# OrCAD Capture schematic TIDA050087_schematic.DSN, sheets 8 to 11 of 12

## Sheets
8 P06: i.MX93 IO/PHY: size C
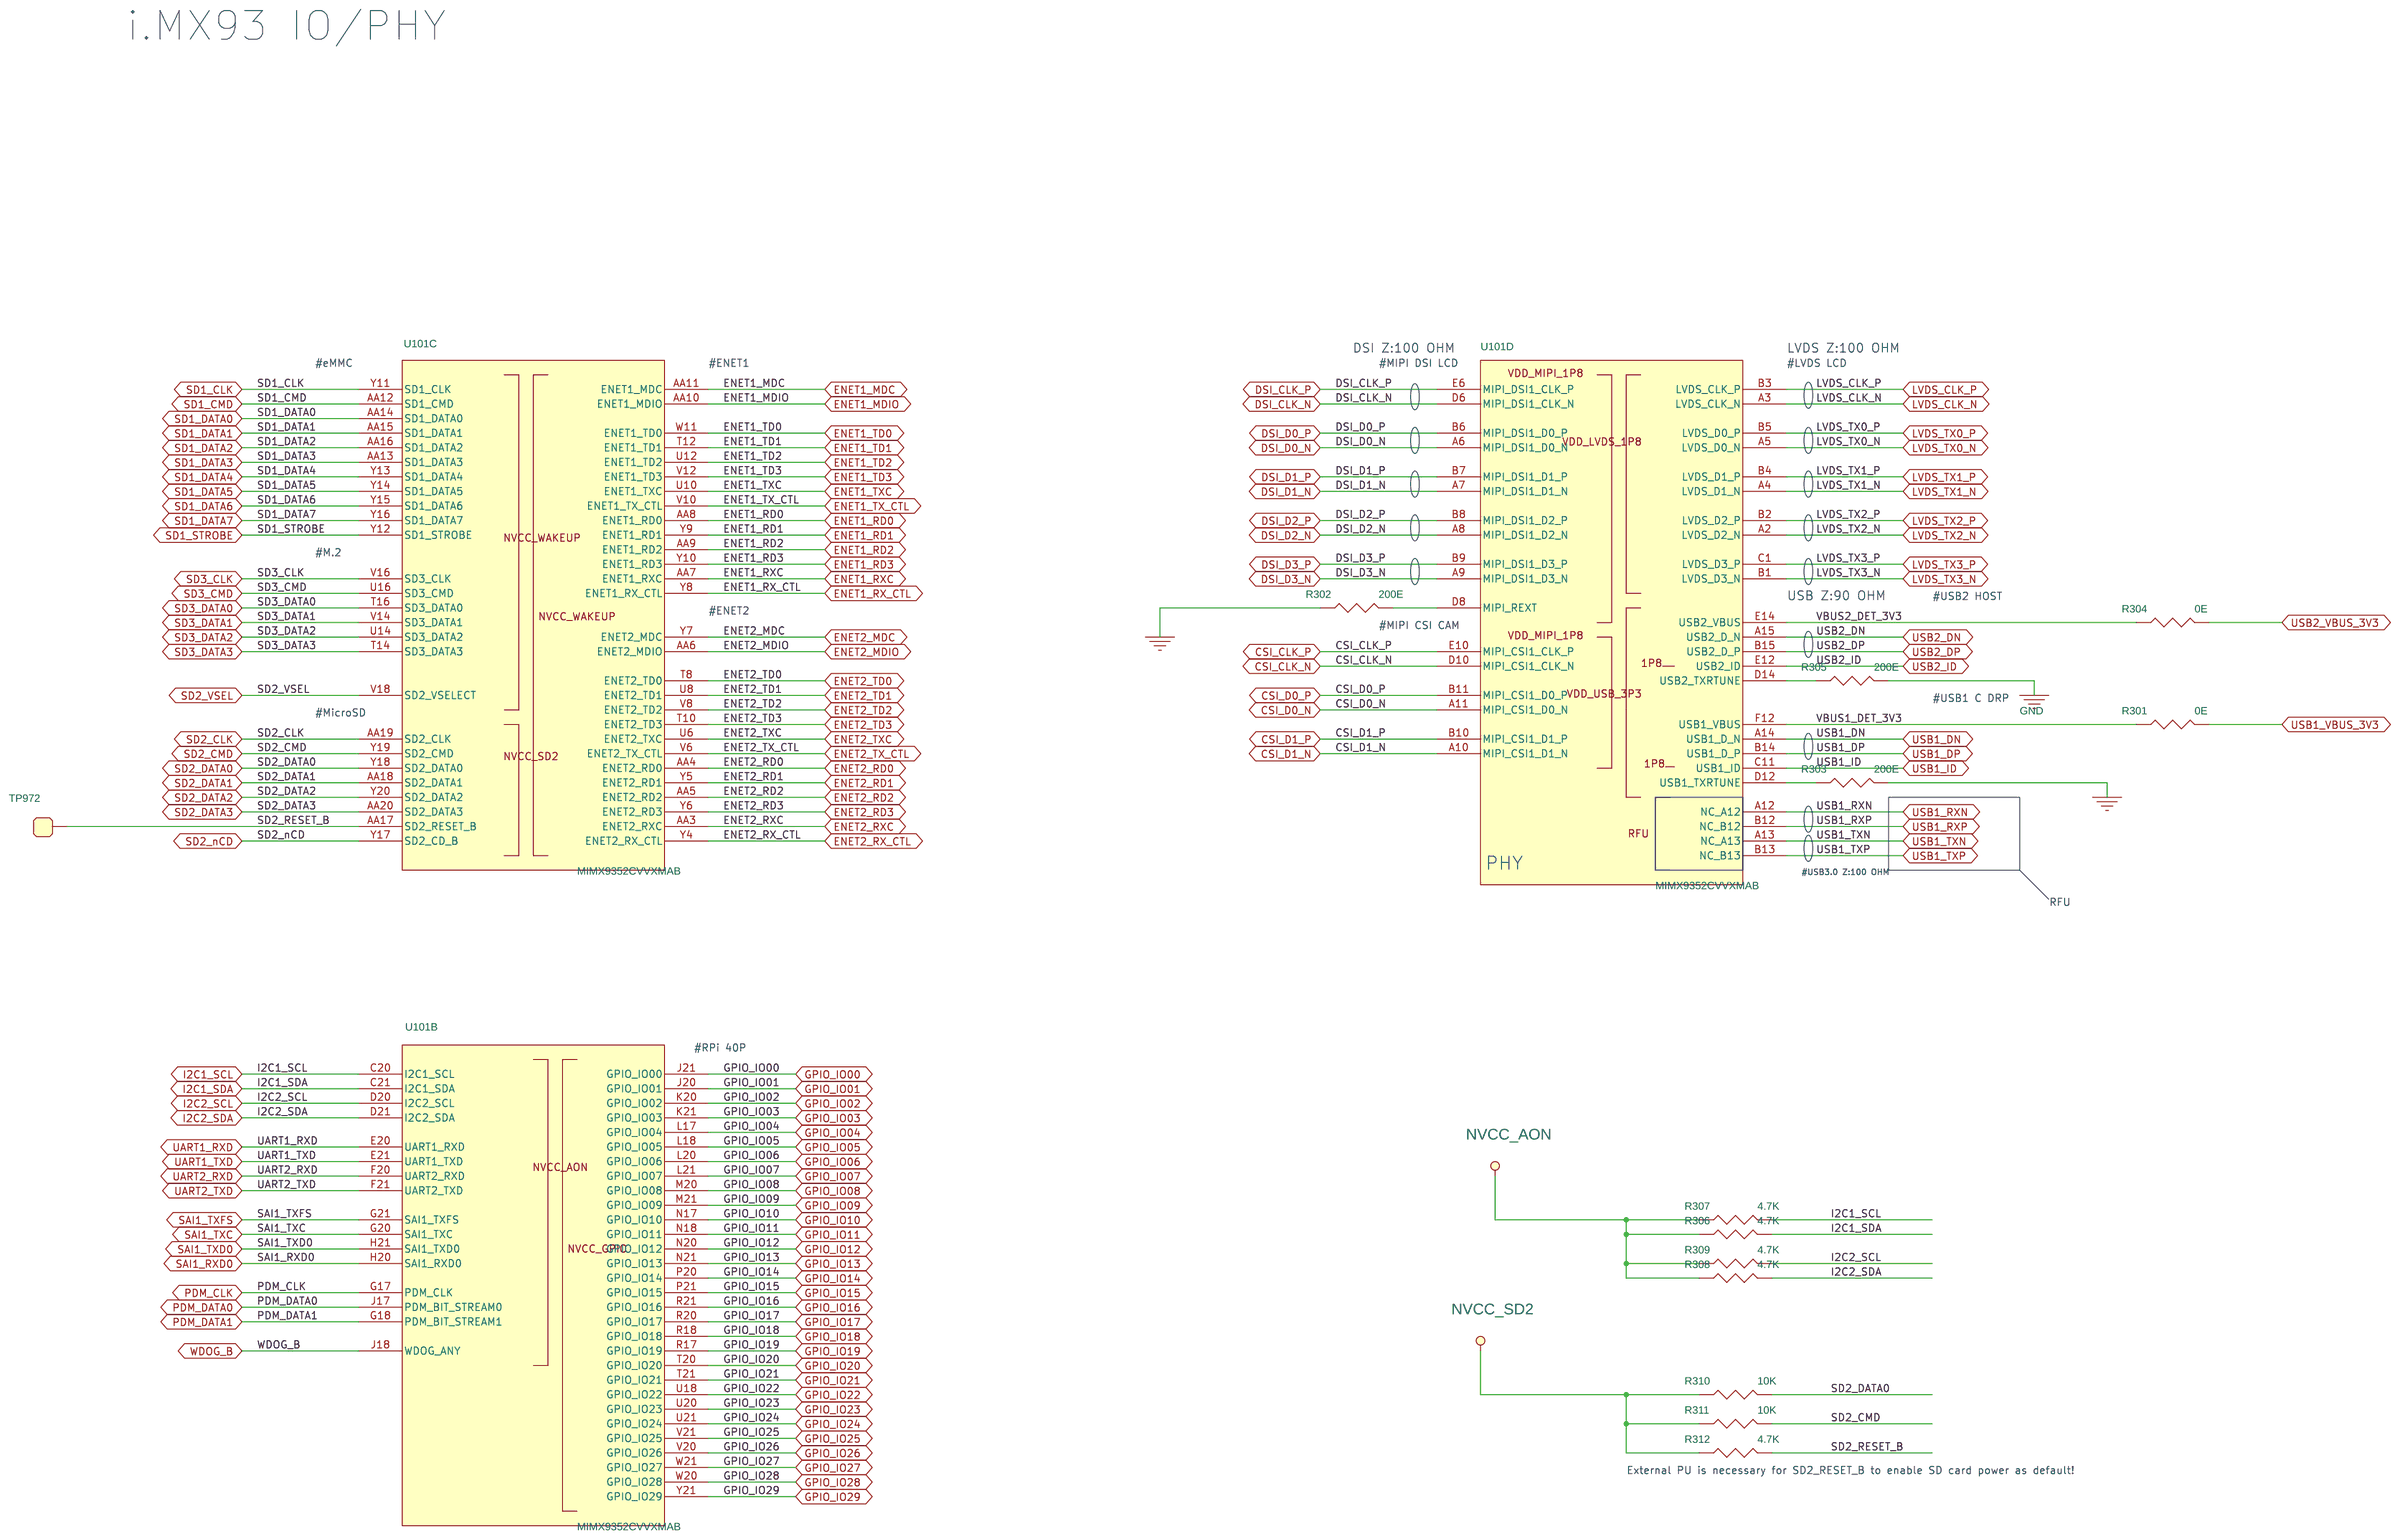
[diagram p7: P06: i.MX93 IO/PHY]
9 P03: POWER ARCHITECTURE
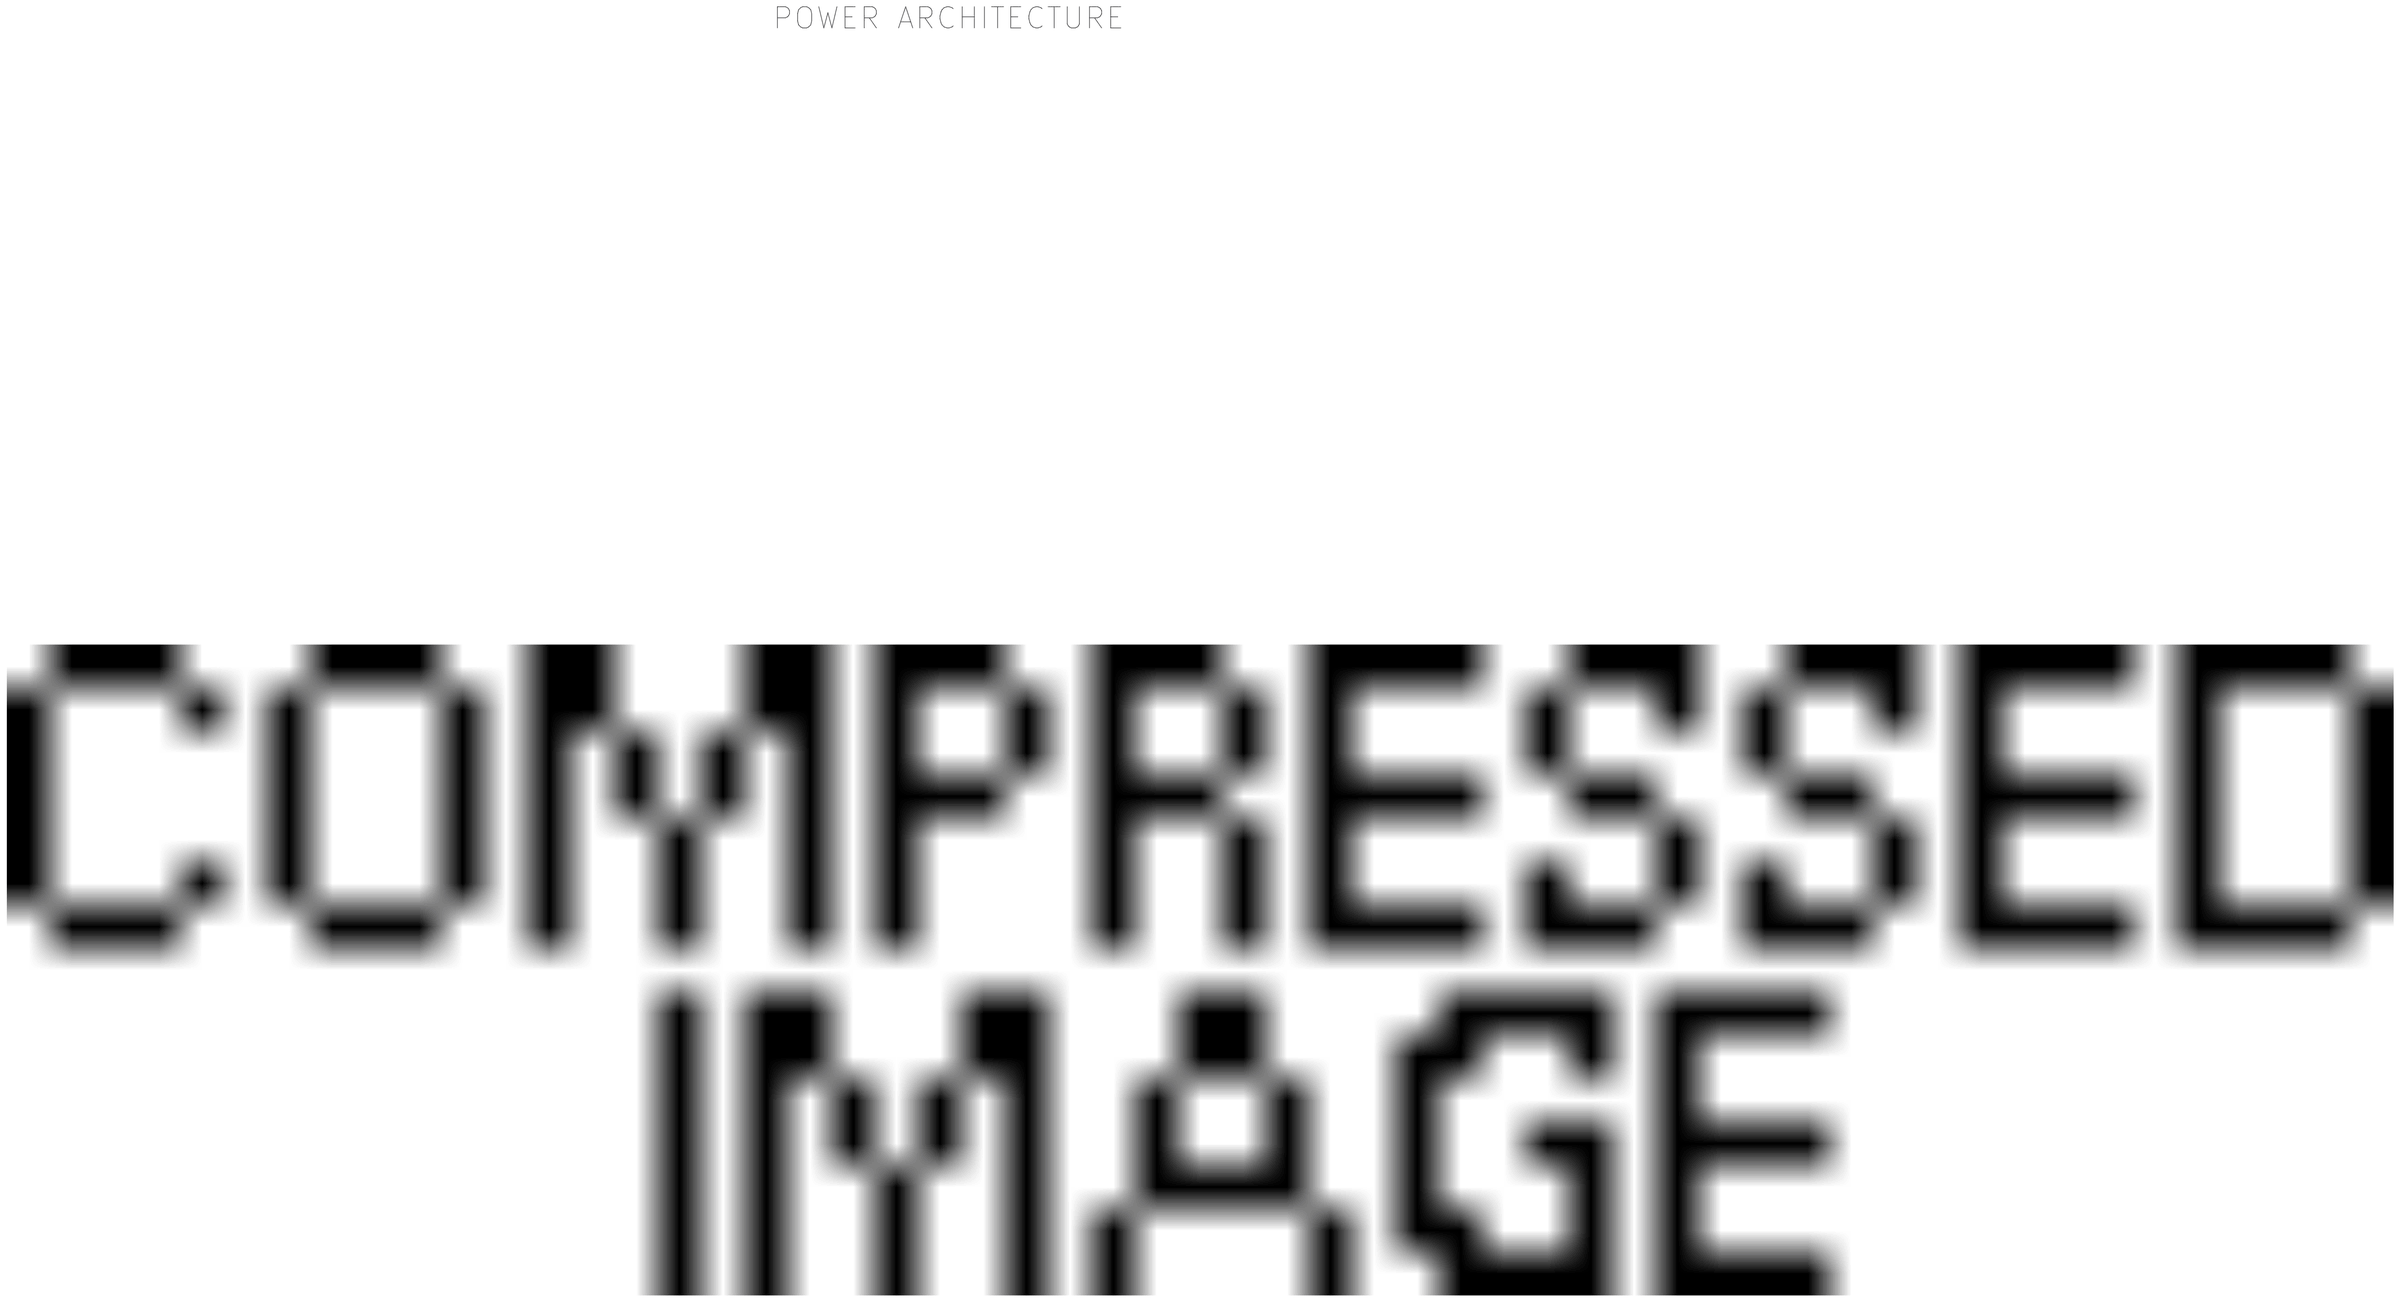
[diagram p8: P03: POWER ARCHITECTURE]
10 P12: POWER MEASUREMENT: size D
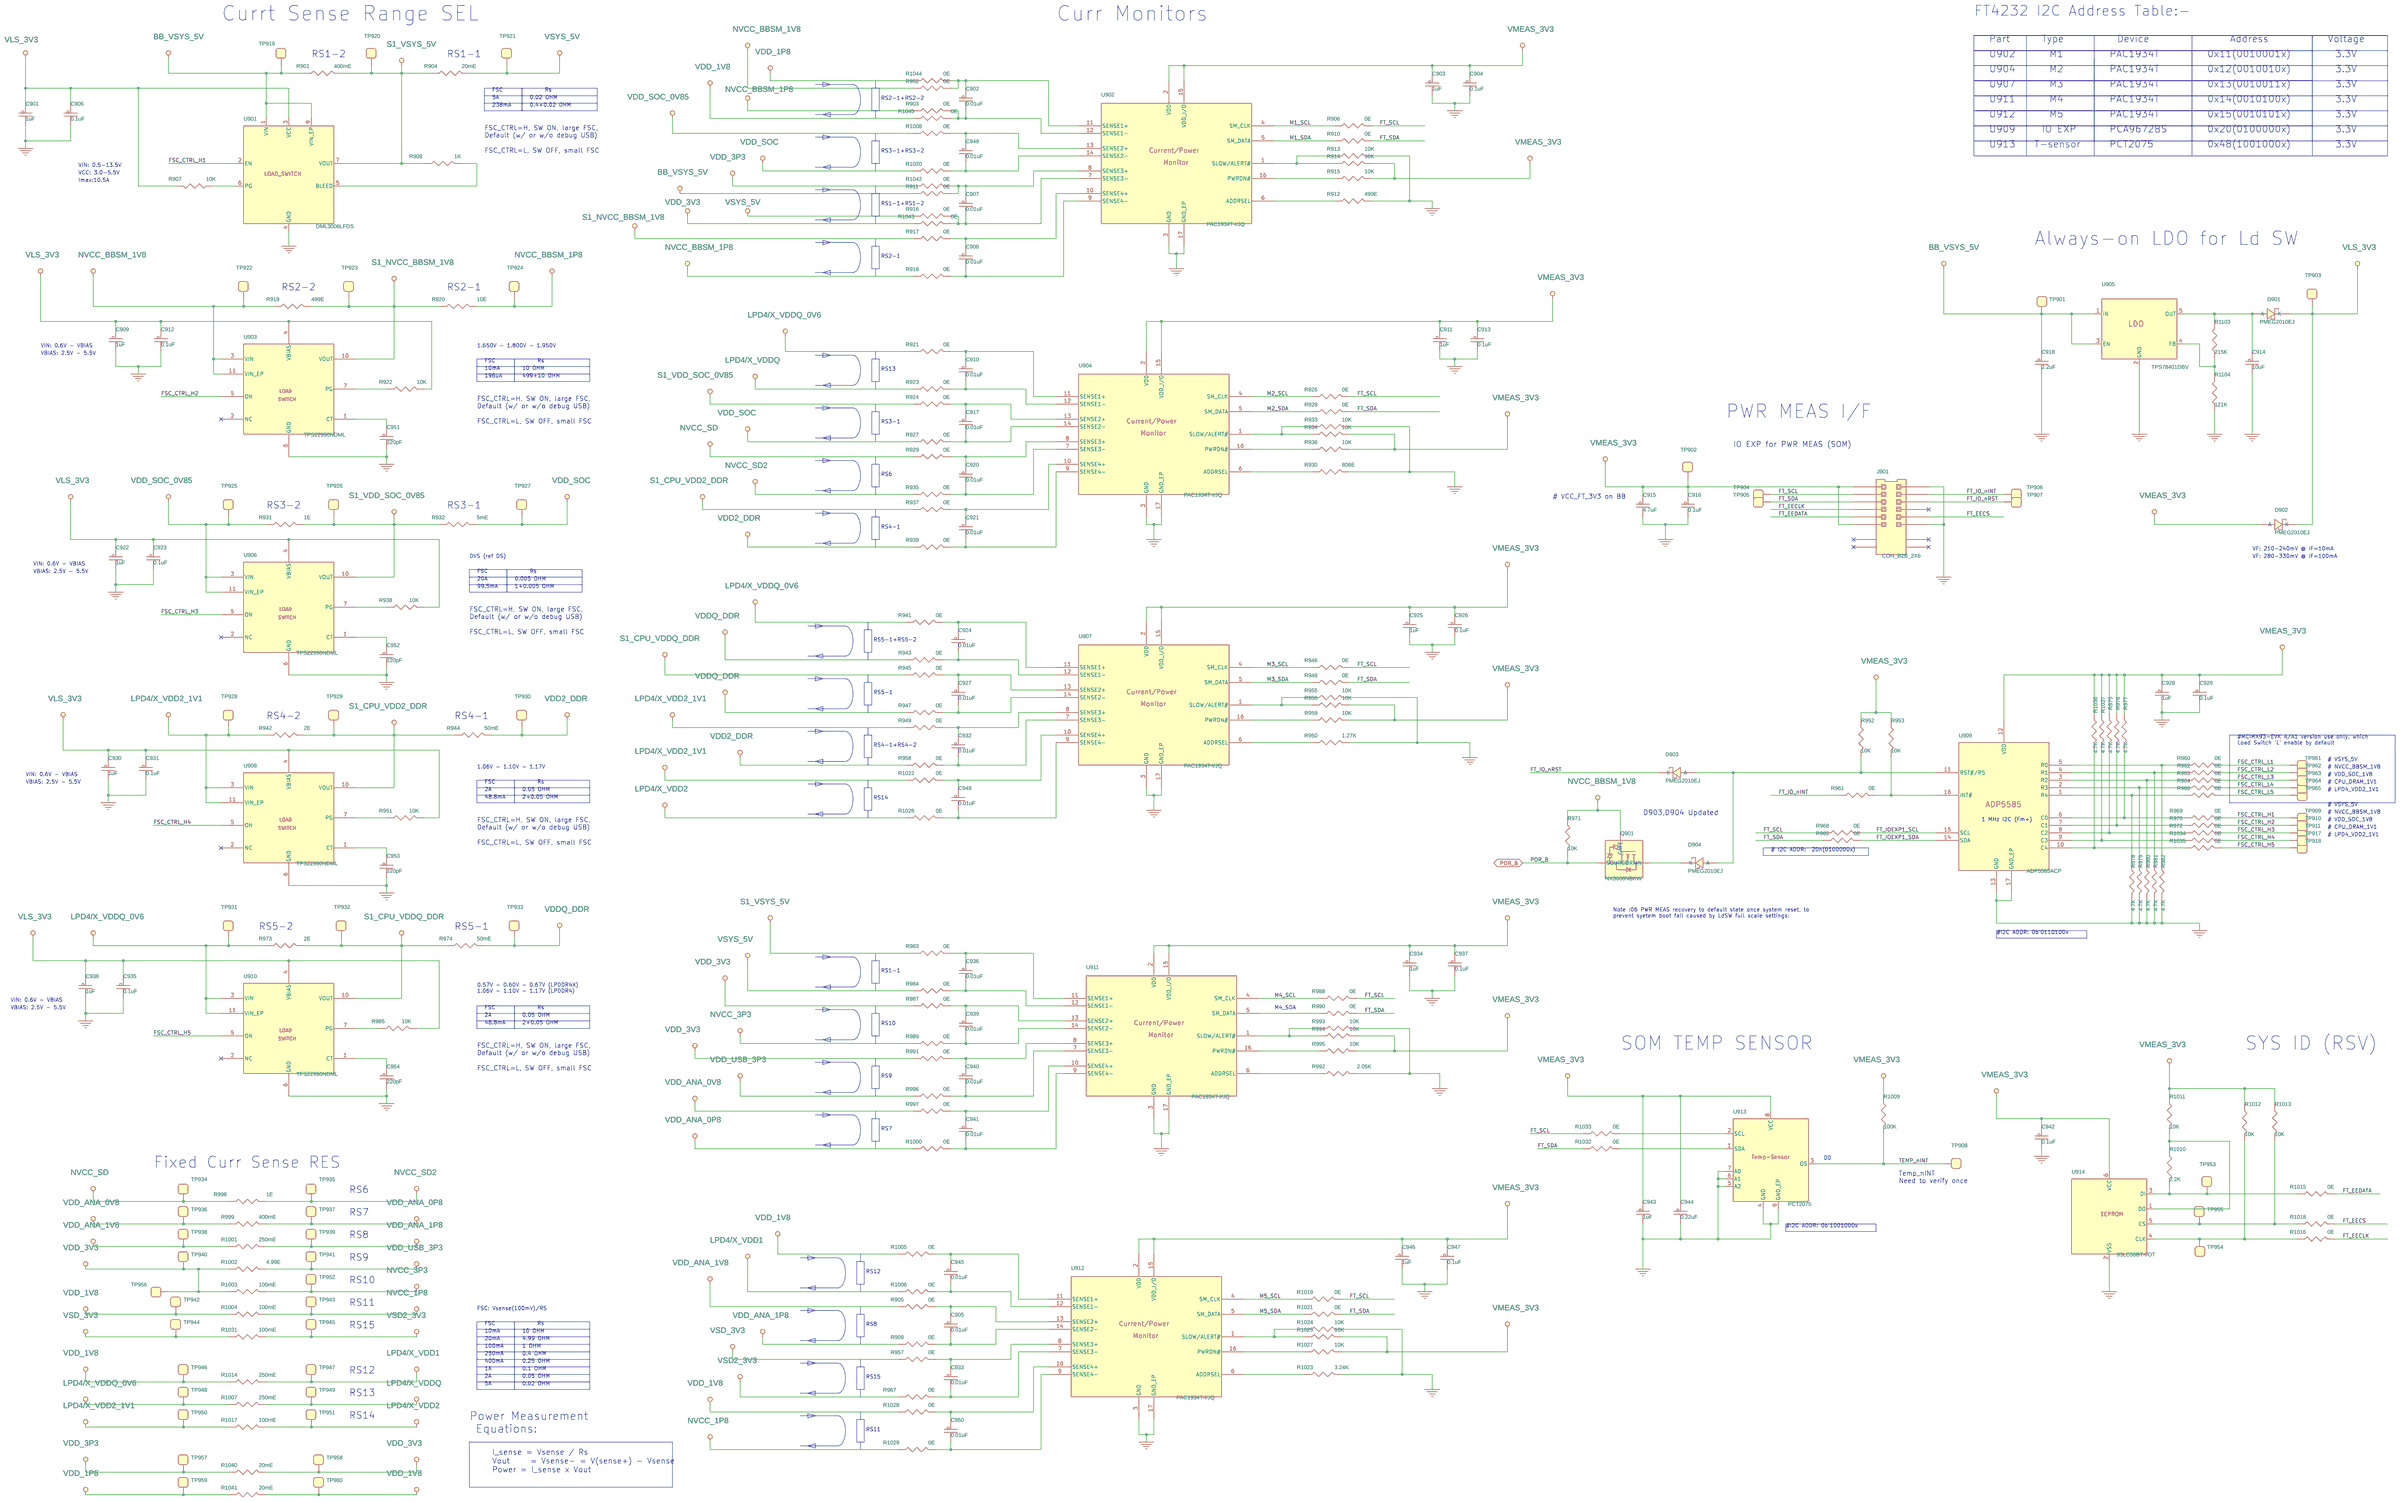
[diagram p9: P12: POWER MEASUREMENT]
11 P02: i.MX93 BLOCK DIAGRAM
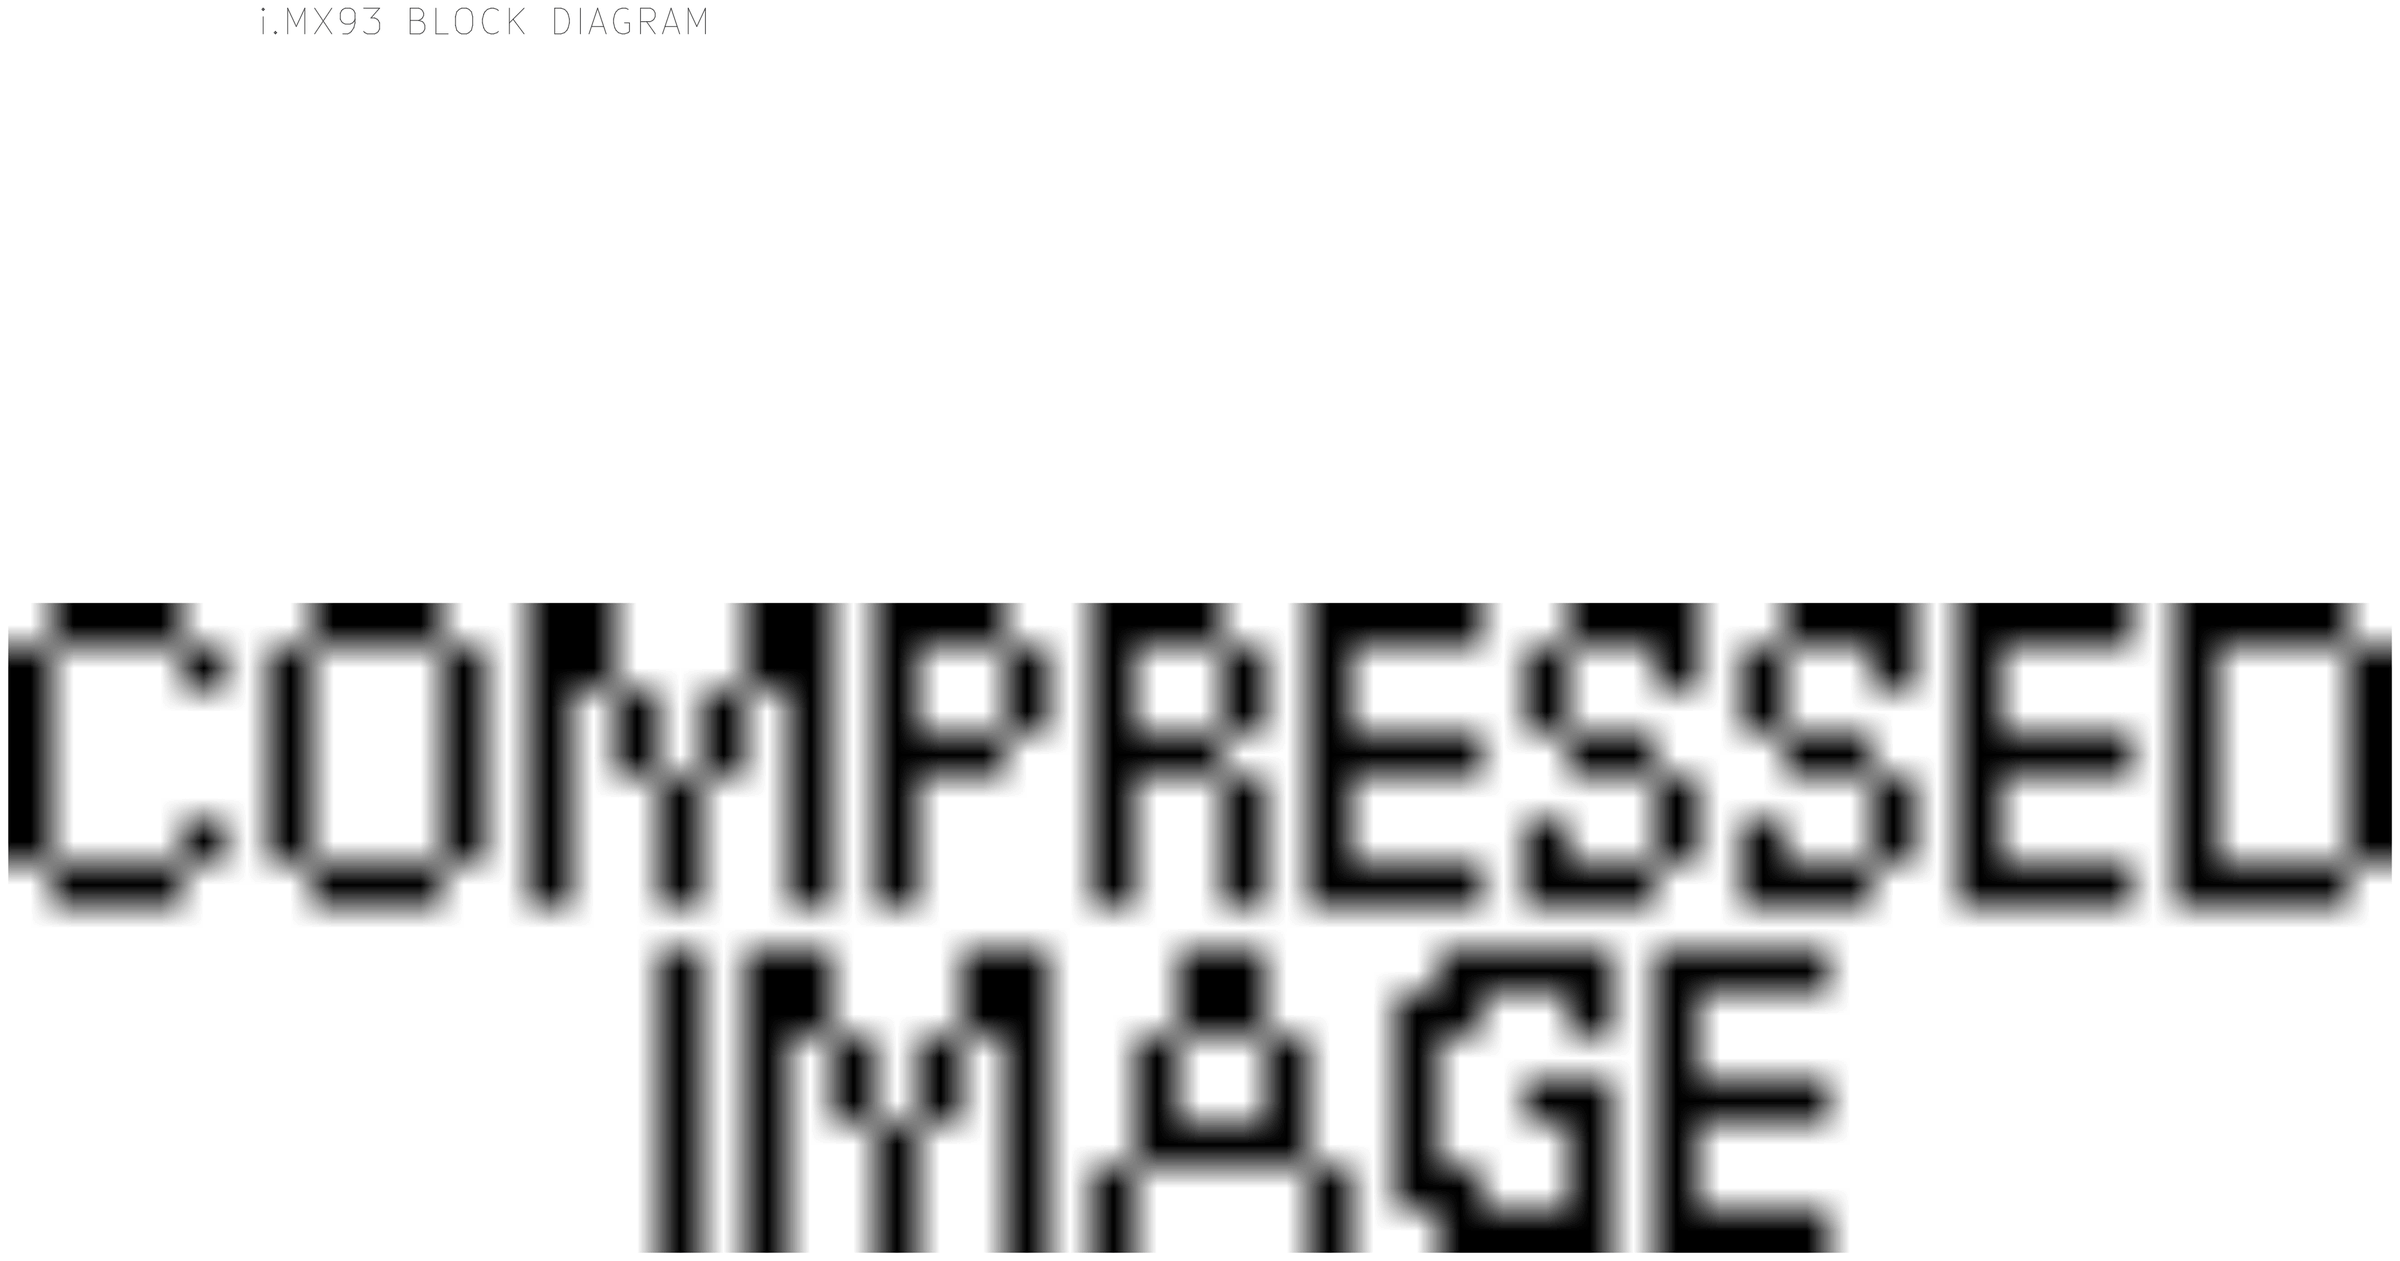
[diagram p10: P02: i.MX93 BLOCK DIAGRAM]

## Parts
sheet P06: i.MX93 IO/PHY
R301  0E  [0201]
R302  200E  [0201]
R303  200E  [0201]
R304  0E  [0201]
R305  200E  [0201]
R306  4.7K  [0402]
R307  4.7K  [0402]
R308  4.7K  [0402]
R309  4.7K  [0402]
R310  10K  [0402]
R311  10K  [0402]
R312  4.7K  [0402]
TP972  SMD  [TP35_SMD]
U101  MIMX9352CVVXMAB  [BGA306_0P5_11X11_CST_A1]  (sections A,B,C,D,E,F)
sheet P12: POWER MEASUREMENT
C901  1uF  [0402]
C902  0.01uF  [0402]
C903  1uF  [0402]
C904  0.1uF  [0402]
C905  0.01uF  [0402]
C906  0.1uF  [0402]
C907  0.01uF  [0402]
C908  0.01uF  [0402]
C909  1uF  [0402]
C910  0.01uF  [0402]
C911  1uF  [0402]
C912  0.1uF  [0402]
C913  0.1uF  [0402]
C914  10uF  [0603]
C915  4.7uF  [0402]
C916  0.1uF  [0402]
C917  0.01uF  [0402]
C918  2.2uF  [0603]
C920  0.01uF  [0402]
C921  0.01uF  [0402]
C922  1uF  [0402]
C923  0.1uF  [0402]
C924  0.01uF  [0402]
C925  1uF  [0402]
C926  0.1uF  [0402]
C927  0.01uF  [0402]
C928  1uF  [0402]
C929  0.1uF  [0402]
C930  1uF  [0402]
C931  0.1uF  [0402]
C932  0.01uF  [0402]
C933  0.01uF  [0402]
C934  1uF  [0402]
C935  0.1uF  [0402]
C936  0.01uF  [0402]
C937  0.1uF  [0402]
C938  1uF  [0402]
C939  0.01uF  [0402]
C940  0.01uF  [0402]
C941  0.01uF  [0402]
C942  0.1uF  [0402]
C943  1uF  [0402]
C944  0.22uF  [0201]
C945  0.01uF  [0402]
C946  1uF  [0402]
C947  0.1uF  [0402]
C948  0.01uF  [0402]
C949  0.01uF  [0402]
C950  0.01uF  [0402]
C951  220pF  [0402]
C952  220pF  [0402]
C953  220pF  [0402]
C954  220pF  [0402]
D901  PMEG2010EJ  [DIO_SOD323F_B_A1]
D902  PMEG2010EJ  [DIO_SOD323F_B_A1]
D903  PMEG2010EJ  [DIO_SOD323F_B_A1]
D904  PMEG2010EJ  [DIO_SOD323F_B_A1]
J901  CON_B2B_2X6  [CON_B2B_2X6M_0P4_SM_ST_A2]
Q901  NX3008NBKW  [SOT323-3L_1P3_2X1P25_A2]
R901  400mE  [RC0603]
R902  0E  [0402]
R903  0E  [0402]
R904  20mE  [RC0805]
R905  0E  [0402]
R906  0E  [0201]
R907  10K  [0402]
R908  1K  [RC0603]
R909  0E  [0402]
R910  0E  [0201]
R911  0E  [0402]
R912  499E  [0402]
R913  10K  [0402]
R914  10K  [0402]
R915  10K  [0402]
R916  0E  [0402]
R917  0E  [0402]
R918  0E  [0402]
R919  499E  [RC0603]
R920  10E  [RC0603]
R921  0E  [0402]
R922  10K  [0402]
R923  0E  [0402]
R924  0E  [0402]
R926  0E  [0201]
R927  0E  [0402]
R928  0E  [0201]
R929  0E  [0402]
R930  806E  [0402]
R931  1E  [RC0603]
R932  5mE  [RC0805]
R933  10K  [0402]
R934  10K  [0402]
R935  0E  [0402]
R936  10K  [0402]
R937  0E  [0402]
R938  10K  [0402]
R939  0E  [0402]
R941  0E  [0402]
R942  2E  [RC0603]
R943  0E  [0402]
R944  50mE  [RC0805]
R945  0E  [0402]
R946  0E  [0201]
R947  0E  [0402]
R948  0E  [0201]
R949  0E  [0402]
R950  1.27K  [0402]
R951  10K  [0402]
R952  10K  [0402]
R953  10K  [0402]
R955  10K  [0402]
R956  10K  [0402]
R957  0E  [0402]
R958  0E  [0402]
R959  10K  [0402]
R960  0E  [0402]
R961  0E  [0402]
R962  0E  [0402]
R963  0E  [0402]
R964  0E  [0402]
R965  0E  [0402]
R966  0E  [0402]
R967  0E  [0402]
R968  0E  [0402]
R969  0E  [0402]
R970  0E  [0402]
R971  10K  [0402]
R972  0E  [0402]
R973  2E  [RC0603]
R974  50mE  [RC0805]
R975  4.7K  [0402]
R976  4.7K  [0402]
R977  4.7K  [0402]
R978  4.7K  [0402]
R979  4.7K  [0402]
R980  4.7K  [0402]
R981  4.7K  [0402]
R982  4.7K  [0402]
R983  0E  [0402]
R984  0E  [0402]
R985  10K  [0402]
R987  0E  [0402]
R988  0E  [0201]
R989  0E  [0402]
R990  0E  [0201]
R991  0E  [0402]
R992  2.05K  [0402]
R993  10K  [0402]
R994  10K  [0402]
R995  10K  [0402]
R996  0E  [0402]
R997  0E  [0402]
R998  1E  [RC0603]
R999  400mE  [RC0603]
R1000  0E  [0402]
R1001  250mE  [RC0805]
R1002  4.99E  [RC0603]
R1003  100mE  [RC0805]
R1004  100mE  [RC0805]
R1005  0E  [0402]
R1006  0E  [0402]
R1007  250mE  [RC0805]
R1008  0E  [0402]
R1009  100K  [0402]
R1010  2.2K  [0402]
R1011  10K  [0402]
R1012  10K  [0402]
R1013  10K  [0402]
R1014  250mE  [RC0805]
R1015  0E  [0402]
R1016  0E  [0402]
R1017  100mE  [RC0805]
R1018  0E  [0402]
R1019  0E  [0201]
R1020  0E  [0402]
R1021  0E  [0201]
R1022  0E  [0402]
R1023  3.24K  [0402]
R1024  10K  [0402]
R1025  10K  [0402]
R1026  0E  [0402]
R1027  10K  [0402]
R1028  0E  [0402]
R1029  0E  [0402]
R1031  100mE  [RC0805]
R1032  0E  [0402]
R1033  0E  [0402]
R1034  0E  [0402]
R1035  0E  [0402]
R1036  4.7K  [0402]
R1037  4.7K  [0402]
R1040  20mE  [RC0805]
R1041  20mE  [RC0805]
R1042  0E  [0402]
R1043  0E  [0402]
R1044  0E  [0402]
R1045  0E  [0402]
R1103  215K  [0402]
R1104  121K  [0402]
TP901  SMD  [TP35_SMD]
TP902  SMD  [TP35_SMD]
TP903  SMD  [TP35_SMD]
TP904  SMD  [TP35_SMD]
TP905  SMD  [TP35_SMD]
TP906  SMD  [TP35_SMD]
TP907  SMD  [TP35_SMD]
TP908  SMD  [TP35_SMD]
TP909  SMD  [TP35_SMD]
TP910  SMD  [TP35_SMD]
TP911  SMD  [TP35_SMD]
TP917  SMD  [TP35_SMD]
TP918  SMD  [TP35_SMD]
TP919  SMD  [TP35_SMD]
TP920  SMD  [TP35_SMD]
TP921  SMD  [TP35_SMD]
TP922  SMD  [TP35_SMD]
TP923  SMD  [TP35_SMD]
TP924  SMD  [TP35_SMD]
TP925  SMD  [TP35_SMD]
TP926  SMD  [TP35_SMD]
TP927  SMD  [TP35_SMD]
TP928  SMD  [TP35_SMD]
TP929  SMD  [TP35_SMD]
TP930  SMD  [TP35_SMD]
TP931  SMD  [TP35_SMD]
TP932  SMD  [TP35_SMD]
TP933  SMD  [TP35_SMD]
TP934  SMD  [TP35_SMD]
TP935  SMD  [TP35_SMD]
TP936  SMD  [TP35_SMD]
TP937  SMD  [TP35_SMD]
TP938  SMD  [TP35_SMD]
TP939  SMD  [TP35_SMD]
TP940  SMD  [TP35_SMD]
TP941  SMD  [TP35_SMD]
TP942  SMD  [TP35_SMD]
TP943  SMD  [TP35_SMD]
TP944  SMD  [TP35_SMD]
TP945  SMD  [TP35_SMD]
TP946  SMD  [TP35_SMD]
TP947  SMD  [TP35_SMD]
TP948  SMD  [TP35_SMD]
TP949  SMD  [TP35_SMD]
TP950  SMD  [TP35_SMD]
TP951  SMD  [TP35_SMD]
TP952  SMD  [TP35_SMD]
TP953  SMD  [TP35_SMD]
TP954  SMD  [TP35_SMD]
TP955  SMD  [TP35_SMD]
TP956  SMD  [TP35_SMD]
TP957  SMD  [TP35_SMD]
TP958  SMD  [TP35_SMD]
TP959  SMD  [TP35_SMD]
TP960  SMD  [TP35_SMD]
TP961  SMD  [TP35_SMD]
TP962  SMD  [TP35_SMD]
TP963  SMD  [TP35_SMD]
TP964  SMD  [TP35_SMD]
TP965  SMD  [TP35_SMD]
U901  DML3006LFDS  [DFN7_0P5_2P05X2P05_EP_A1]
U902  PAC1934T-I/JQ  [UQFN16_0P65_4X4_EP_A1]
U903  TPS22990NDML  [WSON10_0P5_2X3_EP_B_A1]
U904  PAC1934T-I/JQ  [UQFN16_0P65_4X4_EP_A1]
U905  TPS78401DBV  [SOT23-5L_0P95_2P9X1P6_E_A1]
U906  TPS22990NDML  [WSON10_0P5_2X3_EP_B_A1]
U907  PAC1934T-I/JQ  [UQFN16_0P65_4X4_EP_A1]
U908  TPS22990NDML  [WSON10_0P5_2X3_EP_B_A1]
U909  ADP5585ACP  [LFCSP16_0P5_3X3_EP_A_A1]
U910  TPS22990NDML  [WSON10_0P5_2X3_EP_B_A1]
U911  PAC1934T-I/JQ  [UQFN16_0P65_4X4_EP_A1]
U912  PAC1934T-I/JQ  [UQFN16_0P65_4X4_EP_A1]
U913  PCT2075  [SON8_0P5_3X2_EP_A1]
U914  93LC56BT-I/OT  [SOT23-6L_0P95_2P9X1P6_K_A1]

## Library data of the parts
R301 R304 R906 R910 R926 R928 R946 R948 R988 R990 R1019 R1021 = RES: Res, Chip, 0E, 1/20W, 1A, 0201; EN: 101-1-12661; KEY Number: 101-1-12661@1; Mfg: BOURNS INC; Mfg Part No: CR0201-J/-000GLF
R302 R303 R305 = RES: Res, Chip, 200E, 1/20W, 1%, 0201; EN: 101-1-08117; KEY Number: 101-1-08117@1; Mfg: YAGEO CORPORATION; Mfg Part No: RC0201FR-07200RL; Part Status: 1OPEN; RoHS Status: RoHS; Temperature: -55°C to +125°C
R306-R309 R312 R975-R982 R1036 R1037 = RES: Res, Chip, 4.7K, 1/10W, 5%, AEC-Q200, 0402; EN: 101-1-02785; KEY Number: 101-1-02785@1; Mfg: KOA SPEER ELECTRONICS, INC; Mfg Part No: RK73B1ETTP472J; Part Status: 3SILVER; RoHS Status: RoHS; Temperature: -55°C to +155°C
R310 R311 R907 R913-R915 R922 R933 R934 R936 R938 R951-R953 R955 R956 R959 R971 R985 R993-R995 R1011-R1013 R1024 R1025 R1027 = RES: Res, Chip, 10K, 1/16W, 5%, AEC-Q200, 0402; EN: 101-1-04836; KEY Number: 101-1-04836@1; Mfg: VISHAY INTERTECHNOLOGY, INC; Mfg Part No: CRCW040210K0JNED; Part Status: 3SILVER; Temperature: -55°C to +155°C
TP901-TP911 TP917-TP965 TP972 = TEST_POINT_SMD: Testpoint, Pad=0.89mm, SM=0.99mm, SMD; EN: 666-1-00039; KEY Number: 666-1-00039@1; Mfg: NA; Mfg Part No: 666-1-00039; Part Status: 3SILVER
U101 = CST_IC_MIMX93XX_BGA-306P_A1: IC, SoC, i.MX93, ARM Cortex-A55 Dual Core, 1.7GHz, FCBGA-306; EN: 301-1-01081; KEY Number: 301-1-01081@1; Mfg: NXP SEMICONDUCTORS; Part Status: 3SILVER; RoHS Status: RoHS; Temperature: -40°C to +105°C
C901 C903 C909 C911 C922 C925 C928 C930 C934 C938 C943 C946 = CAP_NP: Cap, Cer-X5R, 1uF, 10V, 10%, 0402; EN: 102-1-07252; KEY Number: 102-1-07252@4; Mfg: YAGEO CORPORATION; Mfg Part No: CC0402KRX5R6BB105; Part Status: 3SILVER
C902 C905 C907 C908 C910 C917 C920 C921 C924 C927 C932 C933 C936 C939-C941 C945 C948-C950 = CAP_NP: Cap, Cer-X7R, 0.01uF, 25V, 5%, 0402; EN: 102-1-05202; KEY Number: 102-1-05202@1; Mfg: YAGEO CORPORATION; Mfg Part No: CC0402JRX7R8BB103; Part Status: 3SILVER; Temperature: -55°C to +125°C
C904 C906 C912 C913 C916 C923 C926 C929 C931 C935 C937 C942 C947 = CAP_NP: Cap, Cer-X5R, 0.1uF, 25V, 10%, 0402; EN: 102-1-07356; KEY Number: 102-1-07356@5; Mfg: YAGEO CORPORATION; Mfg Part No: CC0402KRX5R8BB104; Part Status: 3SILVER
C914 = CAP_NP: Cap, Cer-X5R, 10uF, 16V, 10%, 0603; EN: 102-1-02754; KEY Number: 102-1-02754@1; Mfg: MURATA MANUFACTURING CO,LTD; Mfg Part No: GRM188R61C106KAALD; Part Status: 3SILVER; RoHS Status: ROHS; Temperature: -55°C to +85°C
C915 = CAP_NP: Cap, Cer-X5R, 4.7uF, 10V, 10%, 0402; EN: 102-1-07671; KEY Number: 102-1-07671@4; Mfg: SAMSUNG ELECTRO-MECHANICS AMERICA, INC; Mfg Part No: CL05A475KP5NRNC; Part Status: 3SILVER
C918 = CAP_NP: Cap, Cer-X6S, 2.2uF, 16V, 10%, 0603; EN: 102-1-04305; KEY Number: 102-1-04305@1; Mfg: MURATA MANUFACTURING CO,LTD; Mfg Part No: GRM188C81C225KA12D; Part Status: 3SILVER; RoHS Status: RoHS; Temperature: -55°C to +105°C
C944 = CAP_NP: Cap, Cer-X5R, 0.22uF, 10V, 20%, 0201; EN: 102-1-02582; KEY Number: 102-1-02582@1; Mfg: TAIYO YUDEN; Mfg Part No: LMK063BJ224MP-F; Part Status: 3SILVER; Temperature: -55°C to +85°C
C951-C954 = CAP_NP: Cap, Cer-NPO, 220pF, 50V, 5%, 0402; EN: 102-1-05353; KEY Number: 102-1-05353@1; Mfg: KEMET CORPORATION; Mfg Part No: C0402C221J5GAC; Part Status: 3SILVER; RoHS Status: RoHS; Temperature: -55°C to +125°C
D901-D904 = DIODE_SCH: Diode, Schottky, 1A, 20V, AEC-Q100, SOD-323F; EN: 106-2-00598; KEY Number: 106-2-00598@1; Mfg: NEXPERIA; Mfg Part No: PMEG2010EJ,115; Part Status: 3SILVER; RoHS Status: RoHS; Temperature: +150°C Max
J901 = CST_CONN_B2B_2X6_16P_A1: Conn, B2B, Plug, 2x6, 0.4mm, 0.3A, Shrouded, ST, SMD; EN: 201-1-04267; KEY Number: 201-1-04267@1; Mfg: HRS (HIROSE ELECTRIC CO LTD); Mfg Part No: DF40C-12DP-0.4V(51); Part Status: 3SILVER; RoHS Status: RoHS; Temperature: -35°C to +85°C
Q901 = TRANS_NMOS-ENX1_3P_N_A1: Transistor, N-MOSFET, 30V, 0.35A, Vgs=8V, 0.31W, SOT323-3; EN: 107-2-00432; KEY Number: 107-2-00432@1; Mfg: NEXPERIA; Mfg Part No: NX3008NBKW,115; Part Status: 3SILVER; RoHS Status: RoHS; Temperature: -55°C to +150°C
R901 R999 = RES: Res, I-Sense, 400mE, 1/10W, 1%, 800ppm/degC, AEC-Q200, 0603; EN: 101-3-00529; KEY Number: 101-3-00529@1; Mfg: YAGEO CORPORATION; Mfg Part No: RL0603FR-070R4L; Part Status: 3SILVER; RoHS Status: RoHS, Halogen Free; Temperature: -55°C to +155°C
R902 R903 R905 R909 R911 R916-R918 R921 R923 R924 R927 R929 R935 R937 R939 R941 R943 R945 R947 R949 R957 R958 R960-R970 R972 R983 R984 R987 R989 R991 R996 R997 R1000 R1005 R1006 R1008 R1015 R1016 R1018 R1020 R1022 R1026 R1028 R1029 R1032-R1035 R1042-R1045 = RES: Res, Chip, 0E, 1/16W, 5%, 0402; EN: 101-1-08134; KEY Number: 101-1-08134@1; Mfg: YAGEO CORPORATION; Mfg Part No: RC0402JR-070RL; Part Status: 3SILVER; RoHS Status: RoHS; Temperature: -55°C to +155°C
R904 R1040 R1041 = RES: Res, I-Sense, 20mE, 1/4W, 0.5%, 75ppm/degC, AEC-Q200, 0805; EN: 101-3-00530; KEY Number: 101-3-00530@1; Mfg: VISHAY INTERTECHNOLOGY, INC; Mfg Part No: WSL0805R0200DEA18; Part Status: 3SILVER; RoHS Status: RoHS, Pb Free, Halogen Free, Green; Temperature: -65°C to +170°C
R908 = RES: Res, Chip, 1K, 1/10W, 5%, 0603; EN: 101-1-08779; KEY Number: 101-1-08779@1; Mfg: VENKEL CORP; Mfg Part No: CR0603-10W-102JT; Part Status: 3SILVER; RoHS Status: RoHS; Temperature: -55°C to +155°C
R912 = RES: Res, Chip, 499E, 1/16W, 1%, AEC-Q200, 0402; EN: 101-1-13288; KEY Number: 101-1-13288@1; Mfg: ROHM; Mfg Part No: MCR01MZPF4990
R919 = RES: Res, Chip, 499E, 1/10W, 0.1%, 25ppm/degC, AEC-Q200, 0603; EN: 101-1-08691; KEY Number: 101-1-08691@1; Mfg: KOA SPEER ELECTRONICS, INC; Mfg Part No: RN73R1JTTD4990B25; Part Status: 3SILVER; RoHS Status: RoHS; Temperature: -55°C to +155°C
R920 = RES: Res, Chip, 10E, 1/16W, 0.1%, 25ppm/degC, 0603; EN: 101-1-08701; KEY Number: 101-1-08701@1; Mfg: TE CONNECTIVITY; Mfg Part No: CPF0603B10RE1; Part Status: 3SILVER; RoHS Status: RoHS; Temperature: -55°C to +155°C
R930 = RES: Res, Chip, 806E, 1/10W, 1%, AEC-Q200, 0402; EN: 101-1-08689; KEY Number: 101-1-08689@1; Mfg: PANASONIC INDUSTRY CO., LTD; Mfg Part No: ERJ2RKF8060X; Part Status: 3SILVER; RoHS Status: RoHS; Temperature: -55°C to +155°C
R931 R998 = RES: Res, Chip, 1E, 1/10W, 1%, 0603; EN: 101-1-00678; KEY Number: 101-1-00678@1; Mfg: YAGEO CORPORATION; Mfg Part No: RC0603FR-071RL; Part Status: 3SILVER; RoHS Status: ROHS; Temperature: -55°C to +155°C
R932 = RES: Res, I-Sense, 5mE, 1/2W, 1%, 300ppm/degC, AEC-Q200, 0805; EN: 101-3-00126; KEY Number: 101-3-00126@1; Mfg: PANASONIC INDUSTRY CO., LTD; Mfg Part No: ERJ6LWFR005V; Part Status: 3SILVER; Temperature: -55°C to +125°C
R942 R973 = RES: Res, Chip, 2E, 1/8W, 1%, AEC-Q200, 0603; EN: 101-1-00707; KEY Number: 101-1-00707@1; Mfg: KOA SPEER ELECTRONICS, INC; Mfg Part No: RK73H1JTTD2R00F; Part Status: 3SILVER; RoHS Status: ROHS; Temperature: -55°C to +155°C
R944 R974 = RES: Res, I-Sense, 50mE, 1/4W, 1%, 75ppm/degC, AEC-Q200, 0805; EN: 101-3-00177; KEY Number: 101-3-00177@1; Mfg: VISHAY INTERTECHNOLOGY, INC; Mfg Part No: WSL0805R0500FEA18; Part Status: 3SILVER; RoHS Status: RoHS, HalogenFree, Green; Temperature: -65°C to +170°C
R950 = RES: Res, Chip, 1.27K, 1/10W, 1%, AEC-Q200, 0402; EN: 101-1-00303; KEY Number: 101-1-00303@1; Mfg: KOA SPEER ELECTRONICS, INC; Mfg Part No: RK73H1ETTP1271F; Part Status: 3SILVER; RoHS Status: ROHS; Temperature: -55°C to +155°C
R992 = RES: Res, Chip, 2.05K, 1/10W, 1%, AEC-Q200, 0402; EN: 101-1-05689; KEY Number: 101-1-05689@1; Mfg: KOA SPEER ELECTRONICS, INC; Mfg Part No: RK73H1ETTP2051F; Part Status: 3SILVER; RoHS Status: RoHS; Temperature: -55°C to +155°C
R1001 R1007 R1014 = RES: Res, I-Sense, 250mE, 1/8W, 1%, 600ppm/degC, AEC-Q200, 0805; EN: 101-3-00528; KEY Number: 101-3-00528@1; Mfg: YAGEO CORPORATION; Mfg Part No: RL0805FR-070R25L; Part Status: 3SILVER; RoHS Status: RoHS, Halogen Free; Temperature: -55°C to +155°C
R1002 = RES: Res, Chip, 4.99E, 1/16W, 0.1%, 25ppm/degC, 0603; EN: 101-1-08700; KEY Number: 101-1-08700@1; Mfg: TE CONNECTIVITY; Mfg Part No: CPF0603B4R99E1; Part Status: 1OPEN; RoHS Status: RoHS; Temperature: -55°C to +155°C
R1003 R1004 R1017 R1031 = RES: Res, I-Sense, 100mE, 1/4W, 1%, 75ppm/degC, AEC-Q200, 0805; EN: 101-3-00327; KEY Number: 101-3-00327@1; Mfg: VISHAY INTERTECHNOLOGY, INC; Mfg Part No: WSL0805R1000FEA18; Part Status: 3SILVER; RoHS Status: RoHS; Temperature: -65°C to +170°C
R1009 = RES: Res, Chip, 100K, 1/16W, 5%, 0402; EN: 101-1-11924; KEY Number: 101-1-11924@1; Mfg: VENKEL CORP; Mfg Part No: CR0402-16W-104JT
R1010 = RES: Res, Chip, 2.2K, 1/16W, 5%, 0402; EN: 101-1-08699; KEY Number: 101-1-08699@1; Mfg: BOURNS INC; Mfg Part No: CR0402-JW-222GLF; Part Status: 3SILVER; RoHS Status: RoHS; Temperature: -55°C to +155°C
R1023 = RES: Res, Chip, 3.24K, 1/16W, 1%, 0402; EN: 101-1-00342; KEY Number: 101-1-00342@1; Mfg: KOA SPEER ELECTRONICS, INC; Mfg Part No: RK73H1ETTP3241F; Part Status: 3SILVER; Temperature: -55°C to +155°C
R1103 = RES: Res, Chip, 215K, 1/10W, 1%, AEC-Q200, 0402; EN: 101-1-00517; KEY Number: 101-1-00517@1; Mfg: KOA SPEER ELECTRONICS, INC; Mfg Part No: RK73H1ETTP2153F; Part Status: 3SILVER; RoHS Status: ROHS; Temperature: -55°C to +155°C
R1104 = RES: Res, Chip, 121K, 1/10W, 1%, AEC-Q200, 0402; EN: 101-1-00493; KEY Number: 101-1-00493@1; Mfg: KOA SPEER ELECTRONICS, INC; Mfg Part No: RK73H1ETTP1213F; Part Status: 3SILVER; RoHS Status: ROHS; Temperature: -55°C to +155°C
U901 = IC_LOAD_SWITCH_8P_EP_G_A1: IC, DML3006LFDS, Load Switch, 0.5-13.5Vin, 11A, Single Channel, V-DFN2020-8; EN: 301-0-05492; KEY Number: 301-0-05492@1; Mfg: DIODES INCORPORATED; Mfg Part No: DML3006LFDS-7; Part Status: 3SILVER; RoHS Status: RoHS; Temperature: -40°C to +85°C
U902 U904 U907 U911 U912 = IC_PAC1934_16P_EP_A1: IC, PAC1934, 4-Channel Current/Power Monitor with I2C, UQFN-16; EN: 301-0-02854; KEY Number: 301-0-02854@1; Mfg: MICROCHIP TECHNOLOGY INC.; Part Status: 3SILVER; Temperature: -40°C to +150°C
U903 U906 U908 U910 = IC_LOAD_SWITCH_8P_EP_C_A1: IC, TPS22990N, Load Switch, 2.5V-5.5Vin, 10A, WSON-10; EN: 301-0-06295; KEY Number: 301-0-06295@1; Mfg: TEXAS INSTRUMENTS; Mfg Part No: TPS22990NDMLT; Part Status: 3SILVER; RoHS Status: RoHS; Temperature: -40°C to +105°C
U905 = IC_LDO-ADJ_5P_F_A1: IC, LDO, 1.65-6Vin, 1.2-5.5Vout/0.3A, SOT23-5; EN: 301-4-03271; KEY Number: 301-4-03271@1; Mfg: TEXAS INSTRUMENTS; Mfg Part No: TPS78401DBVR; Part Status: 3SILVER; RoHS Status: RoHS; Temperature: -40°C to +150°C
U909 = IC_ADP5585_16P_EP_A1: IC, ADP5585, 10 Input/Output Port Expander and Keypad Decoder, I2C, LFCSP-16; EN: 301-0-06296; KEY Number: 301-0-06296@1; Mfg: ANALOG DEVICES; Mfg Part No: ADP5585ACPZ-00-R7; Part Status: 1OPEN; RoHS Status: RoHS; Temperature: -40°C to +85°C
U913 = IC_TEMP-SENSOR_8P_EP_A_A1: IC, PCT2075, Digital Temperature Sensor, I2C Interface, HWSON-8; EN: 301-0-06297; KEY Number: 301-0-06297@1; Mfg: NXP SEMICONDUCTORS; Mfg Part No: PCT2075TP,147; Part Status: 3SILVER; RoHS Status: RoHS; Temperature: -55°C to +125°C
U914 = IC_EEPROM-3WIRE_6P_A1: IC, EEPROM, 256B, x16bit, 2MHz, 3-Wire, AEC-Q100, SOT-23-6; EN: 301-2-01316; KEY Number: 301-2-01316@1; Mfg: MICROCHIP TECHNOLOGY INC.; Part Status: 3SILVER; RoHS Status: RoHS; Temperature: -40°C to +85°C

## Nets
GND: C901.2 C903.2 C904.2 C906.2 C909.2 C911.2 C912.2 C913.2 C914.2 C915.2 C916.2 C918.2 C922.2 C923.2 C925.2 C926.2 C928.2 C929.2 C930.2 C931.2 C934.2 C935.2 C937.2 C938.2 C942.2 C943.2 C944.2 C946.2 C947.2 C951.2 C952.2 C953.2 C954.2 J901.2 J901.12 R302.1 R303.2 R305.2 R912.2 R913.2 R930.2 R933.2 R950.2 R955.2 R978.2 R979.2 R980.2 R981.2 R982.2 R992.2 R993.2 R1023.2 R1024.2 R1104.1 U901.4(GND) U902.3(GND) U902.17(GND_EP) U903.6(GND) U904.3(GND) U904.17(GND_EP) U905.2(GND) U906.6(GND) U907.3(GND) U907.17(GND_EP) U908.6(GND) U909.13(GND) U909.17(GND_EP) U910.6(GND) U911.3(GND) U911.17(GND_EP) U912.3(GND) U912.17(GND_EP) U913.4(GND) U913.5(A2) U913.6(A1) U913.7(A0) U913.9(GND_EP) U914.2(VSS) ; also on sheet 1 2 3 5 6 7 12
VBUS1_DET_3V3: R301.1 U101.F12(USB1_VBUS)
VBUS2_DET_3V3: R304.1 U101.E14(USB2_VBUS)
VDD2_DDR: R939.1 R944.2 R958.1 TP930.1 ; also on sheet 6
VDD_1P8: R1041.1 R1044.1 TP959.1 ; also on sheet 12
VDD_1V8: R1004.1 R1005.1 R1014.1 R1028.1 R1041.2 R1045.1 TP942.1 TP946.1 TP960.1 ; also on sheet 2 3 5 6 12
VDD_3P3: R1040.1 R1042.1 TP957.1 ; also on sheet 12
VDD_3V3: R987.1 R991.1 R1002.1 R1003.1 R1040.2 R1043.1 TP940.1 TP956.1 TP958.1 ; also on sheet 3 5 6 7 12
VDD_ANA_0P8: R999.2 R1000.1 TP937.1 ; also on sheet 6
VDD_ANA_0V8: R997.1 R999.1 TP936.1 ; also on sheet 6 12
VDD_ANA_1P8: R909.1 R1001.2 TP939.1 ; also on sheet 6
VDD_ANA_1V8: R905.1 R1001.1 TP938.1 ; also on sheet 6
VDD_SOC: R927.1 R932.2 R1020.1 TP927.1 ; also on sheet 6
VDD_SOC_0V85: R931.1 R1008.1 TP925.1 U906.3(VIN) U906.11(VIN_EP) ; also on sheet 6 12
VDD_USB_3P3: R996.1 R1002.2 TP941.1 ; also on sheet 6
VDDQ_DDR: R943.1 R947.1 R974.2 TP933.1 ; also on sheet 6
BB_VSYS_5V: C918.1 R901.1 R911.1 TP901.1 TP919.1 U901.1(VIN) U901.9(VIN_EP) U905.1(IN) U905.3(EN) ; also on sheet 5
CSI_CLK_N: U101.D10(MIPI_CSI1_CLK_N) ; also on sheet 5
CSI_CLK_P: U101.E10(MIPI_CSI1_CLK_P) ; also on sheet 5
CSI_D0_N: U101.A11(MIPI_CSI1_D0_N) ; also on sheet 5
CSI_D0_P: U101.B11(MIPI_CSI1_D0_P) ; also on sheet 5
CSI_D1_N: U101.A10(MIPI_CSI1_D1_N) ; also on sheet 5
CSI_D1_P: U101.B10(MIPI_CSI1_D1_P) ; also on sheet 5
DSI_CLK_N: U101.D6(MIPI_DSI1_CLK_N) ; also on sheet 5
DSI_CLK_P: U101.E6(MIPI_DSI1_CLK_P) ; also on sheet 5
DSI_D0_N: U101.A6(MIPI_DSI1_D0_N) ; also on sheet 5
DSI_D0_P: U101.B6(MIPI_DSI1_D0_P) ; also on sheet 5
DSI_D1_N: U101.A7(MIPI_DSI1_D1_N) ; also on sheet 5
DSI_D1_P: U101.B7(MIPI_DSI1_D1_P) ; also on sheet 5
DSI_D2_N: U101.A8(MIPI_DSI1_D2_N) ; also on sheet 5
DSI_D2_P: U101.B8(MIPI_DSI1_D2_P) ; also on sheet 5
DSI_D3_N: U101.A9(MIPI_DSI1_D3_N) ; also on sheet 5
DSI_D3_P: U101.B9(MIPI_DSI1_D3_P) ; also on sheet 5
ENET1_MDC: U101.AA11(ENET1_MDC) ; also on sheet 5
ENET1_MDIO: U101.AA10(ENET1_MDIO) ; also on sheet 5
ENET1_RD0: U101.AA8(ENET1_RD0) ; also on sheet 5
ENET1_RD1: U101.Y9(ENET1_RD1) ; also on sheet 5
ENET1_RD2: U101.AA9(ENET1_RD2) ; also on sheet 5
ENET1_RD3: U101.Y10(ENET1_RD3) ; also on sheet 5
ENET1_RX_CTL: U101.Y8(ENET1_RX_CTL) ; also on sheet 5
ENET1_RXC: U101.AA7(ENET1_RXC) ; also on sheet 5
ENET1_TD0: U101.W11(ENET1_TD0) ; also on sheet 5
ENET1_TD1: U101.T12(ENET1_TD1) ; also on sheet 5
ENET1_TD2: U101.U12(ENET1_TD2) ; also on sheet 5
ENET1_TD3: U101.V12(ENET1_TD3) ; also on sheet 5
ENET1_TX_CTL: U101.V10(ENET1_TX_CTL) ; also on sheet 5
ENET1_TXC: U101.U10(ENET1_TXC) ; also on sheet 5
ENET2_MDC: U101.Y7(ENET2_MDC) ; also on sheet 5
ENET2_MDIO: U101.AA6(ENET2_MDIO) ; also on sheet 5
ENET2_RD0: U101.AA4(ENET2_RD0) ; also on sheet 5
ENET2_RD1: U101.Y5(ENET2_RD1) ; also on sheet 5
ENET2_RD2: U101.AA5(ENET2_RD2) ; also on sheet 5
ENET2_RD3: U101.Y6(ENET2_RD3) ; also on sheet 5
ENET2_RX_CTL: U101.Y4(ENET2_RX_CTL) ; also on sheet 5
ENET2_RXC: U101.AA3(ENET2_RXC) ; also on sheet 5
ENET2_TD0: U101.T8(ENET2_TD0) ; also on sheet 5
ENET2_TD1: U101.U8(ENET2_TD1) ; also on sheet 5
ENET2_TD2: U101.V8(ENET2_TD2) ; also on sheet 5
ENET2_TD3: U101.T10(ENET2_TD3) ; also on sheet 5
ENET2_TX_CTL: U101.V6(ENET2_TX_CTL) ; also on sheet 5
ENET2_TXC: U101.U6(ENET2_TXC) ; also on sheet 5
FSC_CTRL_H1: R969.2 TP909.1 U901.2(EN)
FSC_CTRL_H2: R970.2 TP910.1 U903.5(ON)
FSC_CTRL_H3: R972.2 TP911.1 U906.5(ON)
FSC_CTRL_H4: R1034.2 TP917.1 U908.5(ON)
FSC_CTRL_H5: R1035.2 TP918.1 U910.5(ON)
FSC_CTRL_L1: R960.2 TP961.1
FSC_CTRL_L2: R962.2 TP962.1
FSC_CTRL_L3: R963.2 TP963.1
FSC_CTRL_L4: R964.2 TP964.1
FSC_CTRL_L5: R966.2 TP965.1
FT_EECLK: J901.7 R1016.2
FT_EECS: J901.10 R1018.2
FT_EEDATA: J901.9 R1015.2
FT_IO_nINT: J901.4 R961.1 TP906.1
FT_IO_nRST: D903.1(K) J901.6 TP907.1
FT_IOEXP1_SCL: R968.2 U909.15(SCL)
FT_IOEXP1_SDA: R965.2 U909.14(SDA)
FT_SCL: J901.3 R906.2 R926.2 R946.2 R968.1 R988.2 R1019.2 R1033.1 TP904.1
FT_SDA: J901.5 R910.2 R928.2 R948.2 R965.1 R990.2 R1021.2 R1032.1 TP905.1
GPIO_IO00: U101.J21(GPIO_IO00) ; also on sheet 5
GPIO_IO01: U101.J20(GPIO_IO01) ; also on sheet 5
GPIO_IO02: U101.K20(GPIO_IO02) ; also on sheet 5
GPIO_IO03: U101.K21(GPIO_IO03) ; also on sheet 5
GPIO_IO04: U101.L17(GPIO_IO04) ; also on sheet 5
GPIO_IO05: U101.L18(GPIO_IO05) ; also on sheet 5
GPIO_IO06: U101.L20(GPIO_IO06) ; also on sheet 5
GPIO_IO07: U101.L21(GPIO_IO07) ; also on sheet 5
GPIO_IO08: U101.M20(GPIO_IO08) ; also on sheet 5
GPIO_IO09: U101.M21(GPIO_IO09) ; also on sheet 5
GPIO_IO10: U101.N17(GPIO_IO10) ; also on sheet 5
GPIO_IO11: U101.N18(GPIO_IO11) ; also on sheet 5
GPIO_IO12: U101.N20(GPIO_IO12) ; also on sheet 5
GPIO_IO13: U101.N21(GPIO_IO13) ; also on sheet 5
GPIO_IO14: U101.P20(GPIO_IO14) ; also on sheet 5
GPIO_IO15: U101.P21(GPIO_IO15) ; also on sheet 5
GPIO_IO16: U101.R21(GPIO_IO16) ; also on sheet 5
GPIO_IO17: U101.R20(GPIO_IO17) ; also on sheet 5
GPIO_IO18: U101.R18(GPIO_IO18) ; also on sheet 5
GPIO_IO19: U101.R17(GPIO_IO19) ; also on sheet 5
GPIO_IO20: U101.T20(GPIO_IO20) ; also on sheet 5
GPIO_IO21: U101.T21(GPIO_IO21) ; also on sheet 5
GPIO_IO22: U101.U18(GPIO_IO22) ; also on sheet 5
GPIO_IO23: U101.U20(GPIO_IO23) ; also on sheet 5
GPIO_IO24: U101.U21(GPIO_IO24) ; also on sheet 5
GPIO_IO25: U101.V21(GPIO_IO25) ; also on sheet 5
GPIO_IO26: U101.V20(GPIO_IO26) ; also on sheet 5
GPIO_IO27: U101.W21(GPIO_IO27) ; also on sheet 5
GPIO_IO28: U101.W20(GPIO_IO28) ; also on sheet 5
GPIO_IO29: U101.Y21(GPIO_IO29) ; also on sheet 5
I2C1_SCL: R307.2 U101.C20(I2C1_SCL) ; also on sheet 5 12
I2C1_SDA: R306.2 U101.C21(I2C1_SDA) ; also on sheet 5 12
I2C2_SCL: R309.2 U101.D20(I2C2_SCL) ; also on sheet 5 12
I2C2_SDA: R308.2 U101.D21(I2C2_SDA) ; also on sheet 5 12
LPD4/x_VDD1: R1006.1 R1014.2 TP947.1 ; also on sheet 2
LPD4/x_VDD2: R1017.2 R1026.1 TP951.1 ; also on sheet 2
LPD4/x_VDD2_1V1: R942.1 R949.1 R1017.1 R1022.1 TP928.1 TP950.1 U908.3(VIN) U908.11(VIN_EP) ; also on sheet 2 6 12
LPD4/x_VDDQ: R923.1 R1007.2 TP949.1 ; also on sheet 2
LPD4/x_VDDQ_0V6: R921.1 R941.1 R973.1 R1007.1 TP931.1 TP948.1 U910.3(VIN) U910.11(VIN_EP) ; also on sheet 2 6 12
LVDS_CLK_N: U101.A3(LVDS_CLK_N) ; also on sheet 5
LVDS_CLK_P: U101.B3(LVDS_CLK_P) ; also on sheet 5
LVDS_TX0_N: U101.A5(LVDS_D0_N) ; also on sheet 5
LVDS_TX0_P: U101.B5(LVDS_D0_P) ; also on sheet 5
LVDS_TX1_N: U101.A4(LVDS_D1_N) ; also on sheet 5
LVDS_TX1_P: U101.B4(LVDS_D1_P) ; also on sheet 5
LVDS_TX2_N: U101.A2(LVDS_D2_N) ; also on sheet 5
LVDS_TX2_P: U101.B2(LVDS_D2_P) ; also on sheet 5
LVDS_TX3_N: U101.B1(LVDS_D3_N) ; also on sheet 5
LVDS_TX3_P: U101.C1(LVDS_D3_P) ; also on sheet 5
M1_SCL: R906.1 U902.4(SM_CLK)
M1_SDA: R910.1 U902.5(SM_DATA)
M2_SCL: R926.1 U904.4(SM_CLK)
M2_SDA: R928.1 U904.5(SM_DATA)
M3_SCL: R946.1 U907.4(SM_CLK)
M3_SDA: R948.1 U907.5(SM_DATA)
M4_SCL: R988.1 U911.4(SM_CLK)
M5_SCL: R1019.1 U912.4(SM_CLK)
M5_SDA: R1021.1 U912.5(SM_DATA)
NVCC_1P8: R1004.2 R1029.1 TP943.1 ; also on sheet 6
NVCC_3P3: R989.1 R1003.2 TP952.1 ; also on sheet 6
NVCC_AON: R306.1 R307.1 R308.1 R309.1 ; also on sheet 5 6 7
NVCC_BBSM_1P8: R903.1 R918.1 R920.2 TP924.1 ; also on sheet 6
NVCC_BBSM_1V8: Q901.1(GATE) R902.1 R919.1 R971.1 TP922.1 U903.3(VIN) U903.11(VIN_EP) ; also on sheet 1 5 6 12
NVCC_SD: R929.1 R998.1 TP934.1 ; also on sheet 6 12
NVCC_SD2: R310.1 R311.1 R312.1 R935.1 R998.2 TP935.1 ; also on sheet 5 6
PDM_CLK: U101.G17(PDM_CLK) ; also on sheet 5
PDM_DATA0: U101.J17(PDM_BIT_STREAM0) ; also on sheet 5
PDM_DATA1: U101.G18(PDM_BIT_STREAM1) ; also on sheet 5
POR_B: Q901.2(SOURCE) R971.2 ; also on sheet 1 5 12
S1_CPU_VDD2_DDR: R937.1 R942.2 R944.1 TP929.1 U908.10(VOUT)
S1_CPU_VDDQ_DDR: R945.1 R973.2 R974.1 TP932.1 U910.10(VOUT)
S1_NVCC_BBSM_1V8: R917.1 R919.2 R920.1 TP923.1 U903.10(VOUT)
S1_VDD_SOC_0V85: R924.1 R931.2 R932.1 TP926.1 U906.10(VOUT)
S1_VSYS_5V: R901.2 R904.1 R908.1 R983.1 TP920.1 U901.7(VOUT)
SAI1_RXD0: U101.H20(SAI1_RXD0) ; also on sheet 5
SAI1_TXC: U101.G20(SAI1_TXC) ; also on sheet 5
SAI1_TXD0: U101.H21(SAI1_TXD0) ; also on sheet 5 7
SAI1_TXFS: U101.G21(SAI1_TXFS) ; also on sheet 5 7
SD1_CLK: U101.Y11(SD1_CLK) ; also on sheet 3
SD1_CMD: U101.AA12(SD1_CMD) ; also on sheet 3
SD1_DATA0: U101.AA14(SD1_DATA0) ; also on sheet 3
SD1_DATA1: U101.AA15(SD1_DATA1) ; also on sheet 3
SD1_DATA2: U101.AA16(SD1_DATA2) ; also on sheet 3
SD1_DATA3: U101.AA13(SD1_DATA3) ; also on sheet 3
SD1_DATA4: U101.Y13(SD1_DATA4) ; also on sheet 3
SD1_DATA5: U101.Y14(SD1_DATA5) ; also on sheet 3
SD1_DATA6: U101.Y15(SD1_DATA6) ; also on sheet 3
SD1_DATA7: U101.Y16(SD1_DATA7) ; also on sheet 3
SD1_STROBE: U101.Y12(SD1_STROBE) ; also on sheet 3
SD2_CLK: U101.AA19(SD2_CLK) ; also on sheet 5
SD2_CMD: R311.2 U101.Y19(SD2_CMD) ; also on sheet 5
SD2_DATA0: R310.2 U101.Y18(SD2_DATA0) ; also on sheet 5
SD2_DATA1: U101.AA18(SD2_DATA1) ; also on sheet 5
SD2_DATA2: U101.Y20(SD2_DATA2) ; also on sheet 5
SD2_DATA3: U101.AA20(SD2_DATA3) ; also on sheet 5
SD2_nCD: U101.Y17(SD2_CD_B) ; also on sheet 5
SD2_RESET_B: R312.2 TP972.1 U101.AA17(SD2_RESET_B)
SD2_VSEL: U101.V18(SD2_VSELECT) ; also on sheet 12
SD3_CLK: U101.V16(SD3_CLK) ; also on sheet 5
SD3_CMD: U101.U16(SD3_CMD) ; also on sheet 5
SD3_DATA0: U101.T16(SD3_DATA0) ; also on sheet 5
SD3_DATA1: U101.V14(SD3_DATA1) ; also on sheet 5
SD3_DATA2: U101.U14(SD3_DATA2) ; also on sheet 5
SD3_DATA3: U101.T14(SD3_DATA3) ; also on sheet 5
TEMP_nINT: R1009.2 TP908.1 U913.3(OS)
UART1_RXD: U101.E20(UART1_RXD) ; also on sheet 5 7
UART1_TXD: U101.E21(UART1_TXD) ; also on sheet 5 7
UART2_RXD: U101.F20(UART2_RXD) ; also on sheet 5 7
UART2_TXD: U101.F21(UART2_TXD) ; also on sheet 5 7
USB1_DN: U101.A14(USB1_D_N) ; also on sheet 5 7
USB1_DP: U101.B14(USB1_D_P) ; also on sheet 5 7
USB1_ID: U101.C11(USB1_ID) ; also on sheet 5
USB1_RXN: U101.A12(NC) ; also on sheet 5
USB1_RXP: U101.B12(NC) ; also on sheet 5
USB1_TXN: U101.A13(NC) ; also on sheet 5
USB1_TXP: U101.B13(NC) ; also on sheet 5
USB1_VBUS_3V3: R301.2 ; also on sheet 5 7
USB2_DN: U101.A15(USB2_D_N) ; also on sheet 5
USB2_DP: U101.B15(USB2_D_P) ; also on sheet 5
USB2_ID: U101.E12(USB2_ID) ; also on sheet 5
USB2_VBUS_3V3: R304.2 ; also on sheet 5
VLS_3V3: C901.1 C906.1 C909.1 C912.1 C922.1 C923.1 C930.1 C931.1 C935.1 C938.1 D901.1(K) D902.1(K) R907.2 R922.2 R938.2 R951.2 R985.2 TP903.1 U901.3(VCC) U903.4(VBIAS) U906.4(VBIAS) U908.4(VBIAS) U910.4(VBIAS)
VMEAS_3V3: C903.1 C904.1 C911.1 C913.1 C915.1 C916.1 C925.1 C926.1 C928.1 C929.1 C934.1 C937.1 C942.1 C943.1 C944.1 C946.1 C947.1 D902.2(A) J901.1 J901.11 R914.2 R915.2 R934.2 R936.2 R952.1 R953.1 R956.2 R959.2 R975.1 R976.1 R977.1 R994.2 R995.2 R1009.1 R1011.1 R1012.1 R1013.1 R1025.2 R1027.2 R1036.1 R1037.1 TP902.1 U902.2(VDD) U902.15(VDD_I/O) U904.2(VDD) U904.15(VDD_I/O) U907.2(VDD) U907.15(VDD_I/O) U909.12(VDD) U911.2(VDD) U911.15(VDD_I/O) U912.2(VDD) U912.15(VDD_I/O) U913.8(VCC) U914.6(VCC)
VSD2_3V3: R967.1 R1031.2 TP945.1 ; also on sheet 5
VSD_3V3: R957.1 R1031.1 TP944.1 ; also on sheet 5 12
VSYS_5V: R904.2 R916.1 R984.1 TP921.1 ; also on sheet 5 7 12
WDOG_B: U101.J18(WDOG_ANY) ; also on sheet 5
N113540349: D903.2(A) D904.2(A) R952.2 U909.11(RST#/R5)
N113540351: R953.2 R961.2 U909.16(INT#)
N113540485: R960.1 R982.1 U909.5(R0)
N113540576: R962.1 R981.1 U909.4(R1)
N113540605: C914.1 D901.2(A) R1103.2 U905.5(OUT)
N113540646: R963.1 R980.1 U909.3(R2)
N113540680: R964.1 R979.1 U909.2(R3)
N113540755: R966.1 R978.1 U909.1(R4)
N113540996: D904.1(K) Q901.3(DRAIN)
N113787187: R915.1 U902.16(PWRDN#)
N113787601: R912.1 U902.6(ADDRSEL)
N113787940: R913.1 R914.1 U902.1(SLOW/ALERT#)
N113791010: C902.1 R902.2 R1044.2 U902.11(SENSE1+)
N113791044: C902.2 R903.2 R1045.2 U902.12(SENSE1-)
N113791152: C907.1 R911.2 R1042.2 U902.8(SENSE3+)
N113791186: C907.2 R916.2 R1043.2 U902.7(SENSE3-)
N113791216: C908.1 R917.2 U902.10(SENSE4+)
N113791250: C908.2 R918.2 U902.9(SENSE4-)
N113798682: C910.1 R921.2 U904.11(SENSE1+)
N113798752: C910.2 R923.2 U904.12(SENSE1-)
N113798791: C917.1 R924.2 U904.13(SENSE2+)
N113798839: C917.2 R927.2 U904.14(SENSE2-)
N113798887: C920.1 R929.2 U904.8(SENSE3+)
N113798893: R930.1 U904.6(ADDRSEL)
N113798925: R933.1 R934.1 U904.1(SLOW/ALERT#)
N113798968: C920.2 R935.2 U904.7(SENSE3-)
N113799011: C921.1 R937.2 U904.10(SENSE4+)
N113799045: C921.2 R939.2 U904.9(SENSE4-)
N113816310: C924.1 R941.2 U907.11(SENSE1+)
N113816380: C924.2 R943.2 U907.12(SENSE1-)
N113816419: C927.1 R945.2 U907.13(SENSE2+)
N113816455: C927.2 R947.2 U907.14(SENSE2-)
N113816503: C932.1 R949.2 U907.8(SENSE3+)
N113816509: R950.1 U907.6(ADDRSEL)
N113816541: R955.1 R956.1 U907.1(SLOW/ALERT#)
N113816573: C932.2 R958.2 U907.7(SENSE3-)
N113819379: C936.1 R983.2 U911.11(SENSE1+)
N113819449: C936.2 R984.2 U911.12(SENSE1-)
N113819488: C939.1 R987.2 U911.13(SENSE2+)
N113819524: C939.2 R989.2 U911.14(SENSE2-)
N113819572: C940.1 R991.2 U911.8(SENSE3+)
N113819642: C940.2 R996.2 U911.7(SENSE3-)
N113819644: R993.1 R994.1 U911.1(SLOW/ALERT#)
N113819688: R995.1 U911.16(PWRDN#)
N113819696: C941.1 R997.2 U911.10(SENSE4+)
N113819730: C941.2 R1000.2 U911.9(SENSE4-)
N113821648: C945.1 R1005.2 U912.11(SENSE1+)
N113821718: C945.2 R1006.2 U912.12(SENSE1-)
N113821847: R1023.1 U912.6(ADDRSEL)
N113821913: R1024.1 R1025.1 U912.1(SLOW/ALERT#)
N113821965: C950.1 R1028.2 U912.10(SENSE4+)
N113821999: C950.2 R1029.2 U912.9(SENSE4-)
N114152142: R302.2 U101.D8(MIPI_REXT)
N114789657: R1012.2 R1016.1 TP954.1 U914.4(CLK)
N114789678: R1013.2 R1018.1 TP955.1 U914.5(CS)
N114814991: R305.1 U101.D14(USB2_TXRTUNE)
N114815134: R303.1 U101.D12(USB1_TXRTUNE)
N115328449: C933.1 R957.2 U912.8(SENSE3+)
N115328489: C933.2 R967.2 U912.7(SENSE3-)
N115328624: C949.1 R1022.2 U907.10(SENSE4+)
N115328664: C949.2 R1026.2 U907.9(SENSE4-)
N115344996: C948.1 R1008.2 U902.13(SENSE2+)
N115345040: C948.2 R1020.2 U902.14(SENSE2-)
N115345198: C905.1 R905.2 U912.13(SENSE2+)
N115345238: C905.2 R909.2 U912.14(SENSE2-)
N115885549: R1010.1 R1011.2 U914.1(DO)
N115885630: R1010.2 R1015.1 TP953.1 U914.3(DI)
N115909883: R969.1 R977.2 U909.6(C0)
N115909890: R970.1 R976.2 U909.7(C1)
N115909893: R972.1 R975.2 U909.8(C2)
N115909896: R1034.1 R1037.2 U909.9(C3)
N115909899: R1035.1 R1036.2 U909.10(C4)
N115939435: C951.1 U903.1(CT)
N115957390: R922.1 U903.7(PG)
N115991020: C952.1 U906.1(CT)
N115994234: R938.1 U906.7(PG)
N115999748: C953.1 U908.1(CT)
N116003893: R951.1 U908.7(PG)
N116014384: C954.1 U910.1(CT)
N116018297: R985.1 U910.7(PG)
N116041401: R908.2 U901.5(BLEED)
N116046959: R907.1 U901.6(PG)
N116083878: R936.1 U904.16(PWRDN#)
N116107496: R959.1 U907.16(PWRDN#)
N116113800: R990.1 U911.5(SM_DATA)
N116121400: R992.1 U911.6(ADDRSEL)
N116137130: R1027.1 U912.16(PWRDN#)
N116701055: R1033.2 U913.2(SCL)
N116701070: R1032.2 U913.1(SDA)
N117032871: R1103.1 R1104.2 U905.4(FB)

Not connected (* = marked no-connect by the designer): J901 8* M1* M2* M3* M4*; U903 2(NC)*; U906 2(NC)*; U908 2(NC)*; U910 2(NC)*

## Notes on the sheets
sheet 8
- i.MX93 IO/PHY
- DSI Z:100 OHM
- LVDS Z:100 OHM
- #eMMC
- #ENET1
- #MIPI DSI LCD
- #LVDS LCD
- #M.2
- USB Z:90 OHM
- #USB2 HOST
- #ENET2
- #MIPI CSI CAM
- #USB1 C DRP
- #MicroSD
- PHY
- #USB3.0 Z:100 OHM
- RFU
- #RPi 40P
- External PU is necessary for SD2_RESET_B to enable SD card power as default!
sheet 9
- POWER ARCHITECTURE
sheet 10
- Currt Sense Range SEL
- Curr Monitors
- FT4232 I2C Address Table:-
- Part
- Type
- Device
- Address
- Voltage
- RS1-2
- RS1-1
- U902
- M1
- PAC1934T
- 0x11(0010001x)
- 3.3V
- U904
- M2
- PAC1934T
- 0x12(0010010x)
- 3.3V
- FSC
- Rs
- U907
- M3
- PAC1934T
- 0x13(0010011x)
- 3.3V
- 5A
- 0.02 OHM
- RS2-1+RS2-2
- U911
- M4
- PAC1934T
- 0x14(0010100x)
- 3.3V
- 238mA
- 0.4+0.02 OHM
- U912
- M5
- PAC1934T
- 0x15(0010101x)
- 3.3V
- FSC_CTRL=H, SW ON, large FSC,
  Default (w/ or w/o debug USB)
- U909
- IO EXP
- PCA9672BS
- 0x20(0100000x)
- 3.3V
- U913
- T-sensor
- PCT2075
- 0x48(1001000x)
- 3.3V
- FSC_CTRL=L, SW OFF, small FSC
- RS3-1+RS3-2
- VIN: 0.5-13.5V
- VCC: 3.0-5.5V
- Imax:10.5A
- RS1-1+RS1-2
- Always-on LDO for Ld SW
- RS2-1
- RS2-2
- RS2-1
- VIN: 0.6V - VBIAS
- 1.650V - 1.800V - 1.950V
- VBIAS: 2.5V - 5.5V
- FSC
- Rs
- 10mA
- 10 OHM
- RS13
- 196uA
- 499+10 OHM
- FSC_CTRL=H, SW ON, large FSC,
  Default (w/ or w/o debug USB)
- PWR MEAS I/F
- FSC_CTRL=L, SW OFF, small FSC
- RS3-1
- IO EXP for PWR MEAS (SOM)
- RS6
- # VCC_FT_3V3 on BB
- RS3-2
- RS3-1
- RS4-1
- VF: 210-240mV @ IF=10mA
- DVS (ref DS)
- VF: 280-330mV @ IF=100mA
- VIN: 0.6V - VBIAS
- VBIAS: 2.5V - 5.5V
- 20A
- FSC
- 0.005 OHM
- Rs
- 99.5mA
- 1+0.005 OHM
- FSC_CTRL=H, SW ON, large FSC,
  Default (w/ or w/o debug USB)
- FSC_CTRL=L, SW OFF, small FSC
- RS5-1+RS5-2
- RS5-1
- RS4-2
- RS4-1
- #MCIMX93-EVK A/A1 version use only, which
  Load Switch 'L' enable by default
- RS4-1+RS4-2
- # VSYS_5V
- VIN: 0.6V - VBIAS
- 1.06V - 1.10V - 1.17V
- # NVCC_BBSM_1V8
- # VDD_SOC_1V8
- VBIAS: 2.5V - 5.5V
- FSC
- Rs
- # CPU_DRAM_1V1
- 2A
- 0.05 OHM
- # LPD4_VDD2_1V1
- 48.8mA
- 2+0.05 OHM
- RS14
- # VSYS_5V
- D903,D904 Updated
- # NVCC_BBSM_1V8
- FSC_CTRL=H, SW ON, large FSC,
  Default (w/ or w/o debug USB)
- 1 MHz I2C (Fm+)
- # CPU_DRAM_1V1
- # VDD_SOC_1V8
- # LPD4_VDD2_1V1
- FSC_CTRL=L, SW OFF, small FSC
- # I2C ADDR:  20h(0100000x)
- Note :06 PWR MEAS recovery to default state once system reset, to
  prevent syetem boot fail caused by LdSW full scale settings;
- RS5-2
- RS5-1
- #I2C ADDR: 0b'0110100x
- RS1-1
- 0.57V - 0.60V - 0.67V (LPDDR4X)
  1.06V - 1.10V - 1.17V (LPDDR4)
- VIN: 0.6V - VBIAS
- VBIAS: 2.5V - 5.5V
- FSC
- Rs
- M4_SDA
- 2A
- 48.8mA
- 0.05 OHM
- 2+0.05 OHM
- RS10
- SOM TEMP SENSOR
- SYS ID (RSV)
- FSC_CTRL=H, SW ON, large FSC,
  Default (w/ or w/o debug USB)
- FSC_CTRL=L, SW OFF, small FSC
- RS9
- RS7
- Fixed Curr Sense RES
- OD
- Temp_nINT
  Need to verify once
- RS6
- RS7
- #I2C ADDR: 0b'1001000x
- RS8
- RS9
- RS12
- RS10
- RS11
- FSC: Vsense(100mV)/RS
- RS15
- FSC
- Rs
- RS8
- 10mA
- 10 OHM
- 20mA
- 4.99 OHM
- 100mA
- 1 OHM
- 250mA
- 400mA
- 0.25 OHM
- 0.4 OHM
- RS12
- 1A
- 0.1 OHM
- 2A
- 0.05 OHM
- RS15
- 5A
- 0.02 OHM
- RS13
- RS14
- Power Measurement
   Equations:
- RS11
- I_sense = Vsense / Rs
  Vout     = Vsense- = V(sense+) - Vsense
  Power = I_sense x Vout
sheet 11
- i.MX93 BLOCK DIAGRAM
